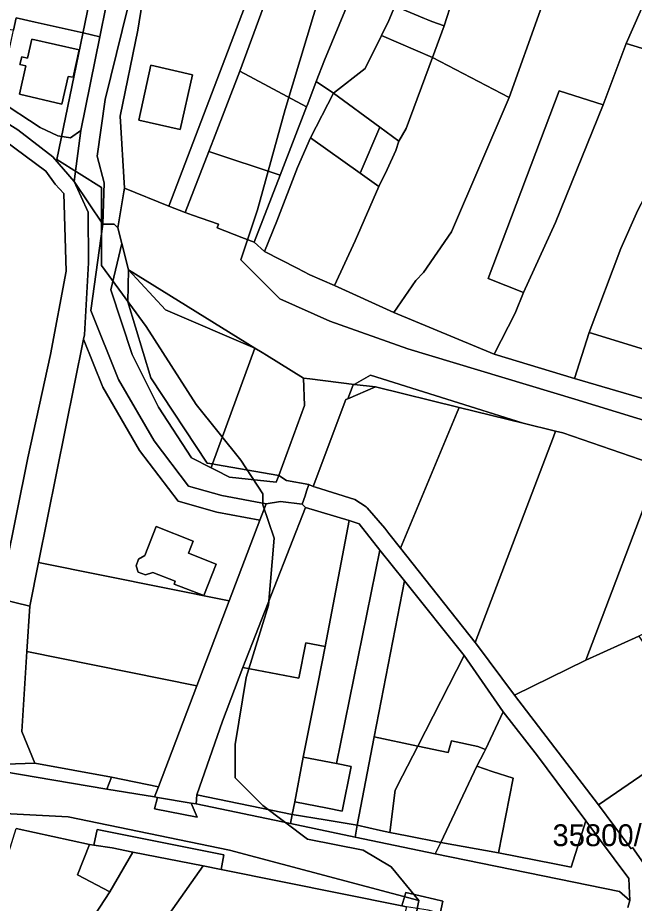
# Model space of a CAD drawing. Extents: x -545779 to -541342, y -1153413 to -1149956.
# Drawn here: x -544345 to -544203.7, y -1151461.6 to -1151258.7 of the extents above; entities that cross this region are included whole.
import ezdxf

# ---------------------------------------------------------------- set-up
doc = ezdxf.new("R2010")
doc.units = 0
for name, color, linetype in [('95560013', 7, 'Continuous'), ('95590013', 7, 'Continuous'), ('95610013', 7, 'Continuous'), ('95630013', 7, 'Continuous'), ('95640013', 7, 'Continuous'), ('95660013', 7, 'Continuous')]:
    doc.layers.add(name, color=color, linetype=linetype)

msp = doc.modelspace()

# ---------------------------------------------------------------- linework, layer by layer
at = {"layer": '95560013'}
for points in [[(-544358.51, -1151276.58), (-544353.61, -1151279.04), (-544353.12, -1151283.1), (-544338.53, -1151293.83), (-544336.38, -1151296.81), (-544334.45, -1151298.99), (-544333.93, -1151316.81), (-544337.5, -1151335.87), (-544342.65, -1151359.51), (-544347.81, -1151384.94), (-544349.21, -1151391.85), (-544356.61, -1151430.05), (-544386.22, -1151427.51), (-544360.6, -1151276)], [(-544332.09, -1151296.26), (-544328.86, -1151303.25), (-544328.78, -1151314.84), (-544329.71, -1151331.38), (-544329.9, -1151332.33), (-544340.23, -1151383.48), (-544342.25, -1151393.49), (-544349.21, -1151391.85), (-544347.81, -1151384.94), (-544342.65, -1151359.51), (-544337.5, -1151335.87), (-544333.93, -1151316.81), (-544334.45, -1151298.99), (-544336.38, -1151296.81), (-544338.53, -1151293.83), (-544353.12, -1151283.1), (-544353.61, -1151279.04), (-544344.97, -1151284.38), (-544336.96, -1151290.58)], [(-544328.22, -1151325.77), (-544321.89, -1151341.58), (-544313.74, -1151355.65), (-544305.84, -1151365.99), (-544298.23, -1151368.17), (-544288.03, -1151370.05), (-544289.48, -1151373.85), (-544299.4, -1151372.02), (-544308.19, -1151369.5), (-544317.07, -1151357.88), (-544325.5, -1151343.33), (-544329.9, -1151332.33), (-544329.71, -1151331.38), (-544328.78, -1151314.84), (-544328.86, -1151303.25), (-544332.09, -1151296.26), (-544325.52, -1151305.99)], [(-544325.5, -1151343.33), (-544317.07, -1151357.88), (-544308.19, -1151369.5), (-544299.4, -1151372.02), (-544289.48, -1151373.85), (-544296.52, -1151392.31), (-544340.23, -1151383.48), (-544329.9, -1151332.33)], [(-544309.16, -1151388.48), (-544302.36, -1151391.08), (-544299.53, -1151383.86), (-544305.85, -1151381.37), (-544304.77, -1151378.59), (-544313.29, -1151375.26), (-544315.88, -1151381.89), (-544317.32, -1151382.78), (-544317.83, -1151384.31), (-544317.41, -1151385.74), (-544315.73, -1151386.35), (-544314.04, -1151385.77), (-544308.89, -1151387.76)], [(-544267.95, -1151509.09), (-544330.23, -1151488.03), (-544321.64, -1151475.91), (-544315.45, -1151471.39), (-544302.52, -1151452.98), (-544298.41, -1151453.81), (-544256.95, -1151462.18), (-544255.94, -1151462.38)]]:
    msp.add_lwpolyline(points, close=True, dxfattribs=at)
at = {"layer": '95590013'}
for points in [[(-544317.48, -1151261.56), (-544310.68, -1151219.21), (-544282.62, -1151229.03), (-544310.36, -1151301.85), (-544320.51, -1151297.8), (-544321.55, -1151281.26)], [(-544278.82, -1151279.15), (-544294.08, -1151270.98), (-544281.27, -1151236.08), (-544264.38, -1151242.96), (-544267.99, -1151252.2), (-544272.99, -1151264.39), (-544274.71, -1151268.41), (-544276.58, -1151273.29), (-544278.55, -1151278.44)], [(-544336.85, -1151254.74), (-544326.33, -1151255.53), (-544324.7, -1151255.9), (-544326.16, -1151263.08), (-544330.01, -1151262.21), (-544341.03, -1151259.73), (-544345.32, -1151258.76), (-544345.94, -1151261.56), (-544359.55, -1151260.12), (-544358.15, -1151252.98), (-544358.05, -1151252.48)], [(-544249.96, -1151267.81), (-544256.01, -1151284.13), (-544257.66, -1151286.99), (-544262, -1151283.8), (-544272.62, -1151276.01), (-544265.41, -1151270.38), (-544261.6, -1151262.8)], [(-544214.06, -1151330.84), (-544217.39, -1151341.34), (-544235.8, -1151335.76), (-544231.01, -1151326.43), (-544229.11, -1151321.68), (-544221.74, -1151305.59), (-544210.83, -1151278.67), (-544205.59, -1151264.63), (-544186.43, -1151270.42), (-544188.28, -1151275.15), (-544202.88, -1151302.79), (-544206.77, -1151311.61)], [(-544267.66, -1151309.79), (-544262.26, -1151297.41), (-544260.35, -1151293.51), (-544258.33, -1151289.17), (-544257.66, -1151286.99), (-544256.01, -1151284.13), (-544249.96, -1151267.81), (-544232.38, -1151276.98), (-544245.59, -1151307.77), (-544252.04, -1151317.08), (-544253.8, -1151318.93), (-544258.81, -1151326.24), (-544272.39, -1151320.03)], [(-544317.27, -1151282.21), (-544307.74, -1151284.33), (-544304.92, -1151271.8), (-544314.47, -1151269.6)], [(-544284.87, -1151294.78), (-544301.19, -1151289.35), (-544300.12, -1151286.59), (-544294.08, -1151270.98), (-544278.82, -1151279.15)], [(-544277.88, -1151286.23), (-544272.62, -1151276.01), (-544262, -1151283.8), (-544266.53, -1151294.35)], [(-544229.11, -1151321.68), (-544237.18, -1151318.45), (-544220.91, -1151275.43), (-544210.83, -1151278.67), (-544221.74, -1151305.59)], [(-544311.14, -1151325.6), (-544290.66, -1151334.39), (-544300.36, -1151360.94), (-544301.59, -1151360.73), (-544314.52, -1151341.22), (-544319.76, -1151323.83), (-544319.64, -1151316.49)], [(-544319.64, -1151316.49), (-544290.66, -1151334.39), (-544311.14, -1151325.6)], [(-544300.36, -1151360.94), (-544290.66, -1151334.39), (-544288.98, -1151335.43), (-544287.98, -1151336.05), (-544279.49, -1151341.29), (-544279.26, -1151347.52), (-544285.19, -1151363.57), (-544299.64, -1151361.07)], [(-544265.13, -1151370.74), (-544267.72, -1151369.06), (-544276.72, -1151366.25), (-544277.27, -1151366.08), (-544269.78, -1151346.21), (-544269.32, -1151346.01), (-544263.04, -1151343.3), (-544243.82, -1151347.99), (-544244.28, -1151349.1), (-544257.27, -1151380.2), (-544259.92, -1151376.85), (-544260.9, -1151375.62), (-544264.92, -1151370.99)], [(-544257.27, -1151380.2), (-544244.28, -1151349.1), (-544243.82, -1151347.99), (-544229.13, -1151351.58), (-544221.72, -1151353.39), (-544222.23, -1151354.73), (-544240.13, -1151401.83)], [(-544220.07, -1151353.81), (-544197.92, -1151361.47), (-544214.8, -1151405.86), (-544231.12, -1151413.87), (-544239.84, -1151402.21), (-544240.13, -1151401.83), (-544222.23, -1151354.73), (-544221.72, -1151353.39)], [(-544184.06, -1151366.1), (-544196.08, -1151397), (-544202.66, -1151400.37), (-544214.8, -1151405.86), (-544197.92, -1151361.47)], [(-544278.98, -1151401.88), (-544280.58, -1151410.03), (-544293.39, -1151407.59), (-544279.01, -1151370.9), (-544269.06, -1151373.86), (-544274.53, -1151402.75)], [(-544274.53, -1151402.75), (-544269.06, -1151373.86), (-544266.73, -1151374.66), (-544261.98, -1151380.65), (-544271.93, -1151429.58), (-544279.58, -1151428.07), (-544278.27, -1151421.65), (-544276.14, -1151410.92)], [(-544256.39, -1151387.69), (-544263.31, -1151423.42), (-544267.18, -1151443.7), (-544274.55, -1151442.49), (-544282.08, -1151441.25), (-544281.48, -1151438.36), (-544274.01, -1151439.82), (-544270.64, -1151440.47), (-544268.6, -1151430.24), (-544271.93, -1151429.58), (-544261.98, -1151380.65)], [(-544253.32, -1151425.56), (-544263.31, -1151423.42), (-544256.39, -1151387.69), (-544242.66, -1151404.79)], [(-544211.87, -1151438.99), (-544231.12, -1151413.87), (-544214.8, -1151405.86), (-544202.66, -1151400.37), (-544191.4, -1151417.5), (-544195.65, -1151419.8), (-544191.7, -1151425.19)], [(-544242.66, -1151404.79), (-544233.72, -1151417.75), (-544237.81, -1151426.35), (-544239.58, -1151425.66), (-544245.58, -1151424.34), (-544246.35, -1151427.05), (-544253.32, -1151425.56)], [(-544239.78, -1151430.15), (-544236.3, -1151431.37), (-544231.43, -1151432.91), (-544234.82, -1151450.04), (-544248.07, -1151447.62)], [(-544331.29, -1151455.07), (-544323.85, -1151458.96), (-544346.93, -1151494.3), (-544356.79, -1151506.85), (-544374.44, -1151524.6), (-544358.92, -1151488.07), (-544345.38, -1151444.48), (-544328.51, -1151448.1)]]:
    msp.add_lwpolyline(points, close=True, dxfattribs=at)
at = {"layer": '95610013'}
for points in [[(-544342.89, -1151403.92), (-544342.25, -1151393.49), (-544340.23, -1151383.48), (-544296.52, -1151392.31), (-544303.94, -1151411.78)], [(-544349.21, -1151391.85), (-544342.25, -1151393.49), (-544342.89, -1151403.92), (-544344.02, -1151422.2), (-544341.1, -1151429.5), (-544356.61, -1151430.05)], [(-544303.94, -1151411.78), (-544312.77, -1151434.93), (-544323.5, -1151432.72), (-544341.1, -1151429.5), (-544344.02, -1151422.2), (-544342.89, -1151403.92)]]:
    msp.add_lwpolyline(points, close=True, dxfattribs=at)
at = {"layer": '95630013'}
for points in [[(-544310.68, -1151219.21), (-544317.48, -1151261.56), (-544321.55, -1151281.26), (-544320.51, -1151297.8), (-544320.65, -1151298.6), (-544322.04, -1151306.84), (-544322.89, -1151306.03), (-544323.14, -1151306.03), (-544324.13, -1151306.01), (-544325.52, -1151305.99), (-544325.19, -1151296.57), (-544326.79, -1151290.45), (-544324.93, -1151277.46), (-544319.79, -1151256.39)], [(-544205.17, -1151462.51), (-544204.74, -1151460.96), (-544204.92, -1151455.91), (-544214.78, -1151442.66), (-544225.87, -1151427.83), (-544233.72, -1151417.75), (-544242.66, -1151404.79), (-544256.39, -1151387.69), (-544261.98, -1151380.65), (-544266.73, -1151374.66), (-544269.06, -1151373.86), (-544279.01, -1151370.9), (-544279.78, -1151370.16), (-544279.14, -1151368.23), (-544278.97, -1151367.71), (-544278.79, -1151367.18), (-544278.29, -1151365.66), (-544277.27, -1151366.08), (-544276.72, -1151366.25), (-544267.72, -1151369.06), (-544265.13, -1151370.74), (-544264.92, -1151370.99), (-544260.9, -1151375.62), (-544259.92, -1151376.85), (-544257.27, -1151380.2), (-544240.13, -1151401.83), (-544239.84, -1151402.21), (-544231.12, -1151413.87), (-544211.87, -1151438.99), (-544204.38, -1151449.08), (-544204.14, -1151448.78), (-544196.56, -1151459.57)]]:
    msp.add_lwpolyline(points, dxfattribs=at)
for points in [[(-544296.44, -1151363.94), (-544285.76, -1151365.11), (-544285.19, -1151363.57), (-544283.37, -1151364.7), (-544278.29, -1151365.66), (-544278.79, -1151367.18), (-544278.97, -1151367.71), (-544279.14, -1151368.23), (-544279.78, -1151370.16), (-544284.74, -1151369.56), (-544288.03, -1151370.05), (-544298.23, -1151368.17), (-544305.84, -1151365.99), (-544313.74, -1151355.65), (-544321.89, -1151341.58), (-544328.22, -1151325.77), (-544325.52, -1151305.99), (-544324.13, -1151306.01), (-544323.14, -1151306.03), (-544322.89, -1151306.03), (-544322.04, -1151306.84), (-544321.15, -1151310.42), (-544323.69, -1151321.04), (-544318.74, -1151335.85), (-544312.7, -1151347.96), (-544305.15, -1151359.53), (-544300.67, -1151361.8), (-544299.57, -1151362.36)], [(-544312.7, -1151347.96), (-544318.74, -1151335.85), (-544323.69, -1151321.04), (-544321.15, -1151310.42), (-544319.64, -1151316.49), (-544319.76, -1151323.83), (-544314.52, -1151341.22), (-544301.59, -1151360.73), (-544300.36, -1151360.94), (-544300.67, -1151361.8), (-544305.15, -1151359.53)], [(-544300.67, -1151361.8), (-544300.36, -1151360.94), (-544299.64, -1151361.07), (-544285.19, -1151363.57), (-544285.76, -1151365.11), (-544296.44, -1151363.94), (-544299.57, -1151362.36)]]:
    msp.add_lwpolyline(points, close=True, dxfattribs=at)
at = {"layer": '95640013'}
for points in [[(-544325.19, -1151296.57), (-544325.52, -1151305.99), (-544332.09, -1151296.26), (-544330.54, -1151284.54), (-544326.16, -1151263.08), (-544324.7, -1151255.9), (-544320.53, -1151230.04), (-544319.5, -1151209.97), (-544319, -1151203.45), (-544317.52, -1151169.14), (-544317.04, -1151147.53), (-544317.86, -1151142.3), (-544318.04, -1151141.16), (-544316.85, -1151140.73), (-544311.08, -1151144.88), (-544311.16, -1151145.77), (-544314.11, -1151209.76), (-544315.77, -1151230.23), (-544317.56, -1151243.24), (-544319.79, -1151256.39), (-544324.93, -1151277.46), (-544326.79, -1151290.45)], [(-544270.44, -1151209), (-544278.93, -1151230.53), (-544281.27, -1151236.08), (-544294.08, -1151270.98), (-544300.12, -1151286.59), (-544301.19, -1151289.35), (-544306.65, -1151303.34), (-544310.36, -1151301.85), (-544282.62, -1151229.03), (-544310.68, -1151219.21), (-544296.94, -1151220.15), (-544295.98, -1151210.19), (-544284.56, -1151211.3), (-544281.03, -1151208.99), (-544271.73, -1151209.97), (-544271.45, -1151208.83)], [(-544233.95, -1151221.19), (-544215.15, -1151228.39), (-544218.13, -1151237.23), (-544232.38, -1151276.98), (-544249.96, -1151267.81), (-544247.29, -1151260.6), (-544245.37, -1151254.55), (-544242.89, -1151247.57), (-544240.19, -1151239.83), (-544239.06, -1151236.62), (-544237.79, -1151232.99), (-544236.76, -1151230.1), (-544237.09, -1151229.98)], [(-544192.11, -1151232.82), (-544195.39, -1151241.43), (-544195.59, -1151241.96), (-544198.2, -1151248.07), (-544200.63, -1151253.34), (-544205.59, -1151264.63), (-544210.83, -1151278.67), (-544220.91, -1151275.43), (-544237.18, -1151318.45), (-544229.11, -1151321.68), (-544231.01, -1151326.43), (-544235.8, -1151335.76), (-544258.81, -1151326.24), (-544253.8, -1151318.93), (-544252.04, -1151317.08), (-544245.59, -1151307.77), (-544232.38, -1151276.98), (-544218.13, -1151237.23), (-544215.15, -1151228.39)], [(-544195.59, -1151241.96), (-544195.39, -1151241.43), (-544192.11, -1151232.82), (-544172.85, -1151235.23), (-544173, -1151235.65), (-544175.98, -1151243.88), (-544176.46, -1151245.09), (-544186.43, -1151270.42), (-544205.59, -1151264.63), (-544200.63, -1151253.34), (-544198.2, -1151248.07)], [(-544183.39, -1151291.3), (-544184.77, -1151291.38), (-544198.77, -1151312.95), (-544197.8, -1151315.18), (-544187.84, -1151320.21), (-544192.28, -1151332.61), (-544200.34, -1151331.28), (-544201.39, -1151334.72), (-544214.06, -1151330.84), (-544206.77, -1151311.61), (-544202.88, -1151302.79), (-544188.28, -1151275.15), (-544186.43, -1151270.42), (-544176.46, -1151245.09), (-544175.98, -1151243.88), (-544173, -1151235.65), (-544172.85, -1151235.23), (-544147.79, -1151238.88), (-544152.83, -1151248.37), (-544158.38, -1151257.07), (-544170.37, -1151278.58), (-544172.24, -1151282.28), (-544178.37, -1151293.74)], [(-544267.99, -1151252.2), (-544264.38, -1151242.96), (-544263.32, -1151240.24), (-544257.78, -1151242.16), (-544252.61, -1151244.35), (-544242.89, -1151247.57), (-544245.37, -1151254.55), (-544247.29, -1151260.6), (-544250.08, -1151259.56), (-544251.02, -1151259.2), (-544251.79, -1151258.91), (-544257.42, -1151256.53), (-544258.6, -1151256.09), (-544262.6, -1151254.38)], [(-544267.99, -1151252.2), (-544262.6, -1151254.38), (-544258.6, -1151256.09), (-544259.95, -1151259.34), (-544261.6, -1151262.8), (-544265.41, -1151270.38), (-544272.62, -1151276.01), (-544276.58, -1151273.29), (-544274.71, -1151268.41), (-544272.99, -1151264.39)], [(-544259.95, -1151259.34), (-544258.6, -1151256.09), (-544257.42, -1151256.53), (-544251.79, -1151258.91), (-544251.02, -1151259.2), (-544250.08, -1151259.56), (-544247.29, -1151260.6), (-544249.96, -1151267.81), (-544261.6, -1151262.8)], [(-544332.89, -1151286.27), (-544335.78, -1151285.78), (-544339.82, -1151283.83), (-544349.44, -1151277.57), (-544346.17, -1151262.61), (-544345.94, -1151261.56), (-544345.32, -1151258.76), (-544341.03, -1151259.73), (-544330.01, -1151262.21), (-544326.16, -1151263.08), (-544330.54, -1151284.54)], [(-544342.74, -1151267.98), (-544344.03, -1151267.65), (-544344.49, -1151269.47), (-544343.1, -1151269.73), (-544344.62, -1151276.24), (-544334.85, -1151278.51), (-544333.4, -1151272.19), (-544332.32, -1151272.35), (-544330.88, -1151266.06), (-544341.77, -1151263.6)], [(-544334.85, -1151278.51), (-544344.62, -1151276.24), (-544343.1, -1151269.73), (-544344.49, -1151269.47), (-544344.03, -1151267.65), (-544342.74, -1151267.98), (-544341.77, -1151263.6), (-544330.88, -1151266.06), (-544332.32, -1151272.35), (-544333.4, -1151272.19)], [(-544317.27, -1151282.21), (-544314.47, -1151269.6), (-544304.92, -1151271.8), (-544307.74, -1151284.33)], [(-544285.65, -1151305.31), (-544288.41, -1151312.26), (-544290.82, -1151310.16), (-544284.87, -1151294.78), (-544278.82, -1151279.15), (-544278.55, -1151278.44), (-544276.58, -1151273.29), (-544272.62, -1151276.01), (-544277.88, -1151286.23), (-544280.91, -1151293.03)], [(-544257.66, -1151286.99), (-544258.33, -1151289.17), (-544260.35, -1151293.51), (-544262.26, -1151297.41), (-544266.53, -1151294.35), (-544262, -1151283.8)], [(-544267.66, -1151309.79), (-544272.39, -1151320.03), (-544278.04, -1151317.64), (-544280.95, -1151316.12), (-544288.41, -1151312.26), (-544285.65, -1151305.31), (-544280.91, -1151293.03), (-544277.88, -1151286.23), (-544266.53, -1151294.35), (-544262.26, -1151297.41)], [(-544284.87, -1151294.78), (-544290.82, -1151310.16), (-544293.65, -1151309.1), (-544299.32, -1151306.86), (-544298.99, -1151306.02), (-544304.91, -1151303.91), (-544306.65, -1151303.34), (-544301.19, -1151289.35)], [(-544201.39, -1151334.72), (-544200.34, -1151331.28), (-544192.28, -1151332.61), (-544192.54, -1151334.15), (-544193.05, -1151337.27), (-544194.14, -1151343.85), (-544194.96, -1151347.93), (-544217.39, -1151341.34), (-544214.06, -1151330.84)], [(-544269.78, -1151346.21), (-544277.27, -1151366.08), (-544278.29, -1151365.66), (-544283.37, -1151364.7), (-544285.19, -1151363.57), (-544279.26, -1151347.52), (-544279.49, -1151341.29), (-544278.08, -1151341.46), (-544267.92, -1151342.7), (-544268.15, -1151342.83), (-544269.32, -1151346.01)], [(-544263.04, -1151343.3), (-544267.92, -1151342.7), (-544264.14, -1151340.57), (-544229.13, -1151351.58), (-544243.82, -1151347.99)], [(-544267.92, -1151342.7), (-544263.04, -1151343.3), (-544269.32, -1151346.01), (-544268.15, -1151342.83)], [(-544293.39, -1151407.59), (-544298.08, -1151419.85), (-544303.98, -1151436.74), (-544304.11, -1151438.8), (-544305.28, -1151438.61), (-544312.98, -1151437.32), (-544313.64, -1151437.21), (-544312.77, -1151434.93), (-544303.94, -1151411.78), (-544296.52, -1151392.31), (-544289.48, -1151373.85), (-544288.03, -1151370.05), (-544284.74, -1151369.56), (-544279.78, -1151370.16), (-544279.01, -1151370.9)], [(-544317.32, -1151382.78), (-544315.88, -1151381.89), (-544313.29, -1151375.26), (-544304.77, -1151378.59), (-544305.85, -1151381.37), (-544299.53, -1151383.86), (-544302.36, -1151391.08), (-544309.16, -1151388.48), (-544308.89, -1151387.76), (-544314.04, -1151385.77), (-544315.73, -1151386.35), (-544317.41, -1151385.74), (-544317.83, -1151384.31)], [(-544293.39, -1151407.59), (-544280.58, -1151410.03), (-544278.98, -1151401.88), (-544274.53, -1151402.75), (-544276.14, -1151410.92), (-544278.27, -1151421.65), (-544279.58, -1151428.07), (-544281.48, -1151438.36), (-544282.08, -1151441.25), (-544303.98, -1151436.74), (-544298.08, -1151419.85)], [(-544237.81, -1151426.35), (-544233.72, -1151417.75), (-544225.87, -1151427.83), (-544214.78, -1151442.66), (-544218.14, -1151453.31), (-544222.02, -1151452.57), (-544234.82, -1151450.04), (-544231.43, -1151432.91), (-544236.3, -1151431.37), (-544239.78, -1151430.15), (-544238.13, -1151426.97)], [(-544263.31, -1151423.42), (-544253.32, -1151425.56), (-544256.85, -1151432.41), (-544258.52, -1151435.68), (-544259.72, -1151445.33), (-544261.88, -1151444.9), (-544267.18, -1151443.7)], [(-544256.85, -1151432.41), (-544253.32, -1151425.56), (-544246.35, -1151427.05), (-544245.58, -1151424.34), (-544239.58, -1151425.66), (-544237.81, -1151426.35), (-544238.13, -1151426.97), (-544239.78, -1151430.15), (-544248.07, -1151447.62), (-544255.75, -1151446.11), (-544259.72, -1151445.33), (-544258.52, -1151435.68)], [(-544187.56, -1151430.91), (-544181.53, -1151438.55), (-544179.83, -1151440.76), (-544175.55, -1151448.78), (-544192.77, -1151457.73), (-544196.56, -1151459.57), (-544204.14, -1151448.78), (-544204.38, -1151449.08), (-544211.87, -1151438.99), (-544191.7, -1151425.19)], [(-544281.48, -1151438.36), (-544279.58, -1151428.07), (-544271.93, -1151429.58), (-544268.6, -1151430.24), (-544270.64, -1151440.47), (-544274.01, -1151439.82)], [(-544341.1, -1151429.5), (-544323.5, -1151432.72), (-544324.56, -1151435.4), (-544356.61, -1151430.05)], [(-544324.56, -1151435.4), (-544323.5, -1151432.72), (-544312.77, -1151434.93), (-544313.64, -1151437.21)], [(-544303.87, -1151441.87), (-544313.68, -1151439.94), (-544312.98, -1151437.32), (-544305.28, -1151438.61)], [(-544282.51, -1151443.31), (-544304.11, -1151438.8), (-544303.98, -1151436.74), (-544282.08, -1151441.25)], [(-544267.69, -1151446.4), (-544282.51, -1151443.31), (-544282.08, -1151441.25), (-544274.55, -1151442.49), (-544267.18, -1151443.7)], [(-544214.78, -1151442.66), (-544204.92, -1151455.91), (-544204.74, -1151460.96), (-544207.08, -1151458.91), (-544249.31, -1151450.22), (-544248.07, -1151447.62), (-544234.82, -1151450.04), (-544222.02, -1151452.57), (-544218.14, -1151453.31)], [(-544323.36, -1151448.87), (-544327.52, -1151448.25), (-544326.81, -1151444.64), (-544297.78, -1151450.46), (-544298.41, -1151453.81), (-544302.52, -1151452.98), (-544318.6, -1151449.9)], [(-544267.69, -1151446.4), (-544267.18, -1151443.7), (-544261.88, -1151444.9), (-544259.72, -1151445.33), (-544255.75, -1151446.11), (-544248.07, -1151447.62), (-544249.31, -1151450.22)], [(-544331.29, -1151455.07), (-544328.51, -1151448.1), (-544327.52, -1151448.25), (-544323.36, -1151448.87), (-544318.6, -1151449.9), (-544323.85, -1151458.96)], [(-544256.95, -1151462.18), (-544256.08, -1151459.1), (-544249.52, -1151460.65), (-544247.56, -1151461.12), (-544248.15, -1151463.92), (-544250.9, -1151463.17), (-544255.94, -1151462.38)]]:
    msp.add_lwpolyline(points, close=True, dxfattribs=at)
for points in [[(-544517.96, -1151238.54), (-544416.31, -1151258.67), (-544376.33, -1151267.55), (-544361.72, -1151271.16), (-544352.01, -1151275.9), (-544349.44, -1151277.57), (-544339.82, -1151283.83), (-544335.78, -1151285.78), (-544332.89, -1151286.27), (-544330.54, -1151284.54), (-544332.09, -1151296.26), (-544336.96, -1151290.58), (-544344.97, -1151284.38), (-544353.61, -1151279.04), (-544358.51, -1151276.58), (-544360.6, -1151276), (-544376.21, -1151271.68), (-544380.12, -1151272.95), (-544381.96, -1151272.53), (-544406.01, -1151267.06), (-544518.88, -1151243.65)], [(-544197.92, -1151361.47), (-544220.07, -1151353.81), (-544221.72, -1151353.39), (-544229.13, -1151351.58), (-544264.14, -1151340.57), (-544267.92, -1151342.7), (-544278.08, -1151341.46), (-544279.49, -1151341.29), (-544287.98, -1151336.05), (-544288.98, -1151335.43), (-544290.66, -1151334.39), (-544319.64, -1151316.49), (-544321.15, -1151310.42), (-544322.04, -1151306.84), (-544320.65, -1151298.6), (-544320.51, -1151297.8), (-544310.36, -1151301.85), (-544306.65, -1151303.34), (-544304.91, -1151303.91), (-544298.99, -1151306.02), (-544299.32, -1151306.86), (-544293.65, -1151309.1), (-544290.82, -1151310.16), (-544288.41, -1151312.26), (-544280.95, -1151316.12), (-544278.04, -1151317.64), (-544272.39, -1151320.03), (-544258.81, -1151326.24), (-544235.8, -1151335.76), (-544217.39, -1151341.34), (-544194.96, -1151347.93)], [(-544356.61, -1151430.05), (-544324.56, -1151435.4), (-544313.64, -1151437.21), (-544312.98, -1151437.32), (-544313.68, -1151439.94), (-544303.87, -1151441.87), (-544305.28, -1151438.61), (-544304.11, -1151438.8), (-544282.51, -1151443.31), (-544267.69, -1151446.4), (-544249.31, -1151450.22), (-544207.08, -1151458.91), (-544204.74, -1151460.96), (-544205.17, -1151462.51)], [(-544248.15, -1151463.92), (-544247.56, -1151461.12), (-544249.52, -1151460.65), (-544256.08, -1151459.1), (-544256.95, -1151462.18), (-544298.41, -1151453.81), (-544297.78, -1151450.46), (-544326.81, -1151444.64), (-544327.52, -1151448.25), (-544328.51, -1151448.1), (-544345.38, -1151444.48)], [(-544455.29, -1151722.05), (-544425.47, -1151635.75), (-544402.51, -1151579.84), (-544385.47, -1151546.37), (-544374.44, -1151524.6), (-544356.79, -1151506.85), (-544346.93, -1151494.3), (-544323.85, -1151458.96), (-544318.6, -1151449.9), (-544302.52, -1151452.98), (-544315.45, -1151471.39), (-544321.64, -1151475.91), (-544330.23, -1151488.03), (-544348.98, -1151514.49), (-544374.27, -1151550.18), (-544385.88, -1151566.12), (-544411.63, -1151619.63), (-544415.57, -1151630.49), (-544431.97, -1151675.83)]]:
    msp.add_lwpolyline(points, dxfattribs=at)
at = {"layer": '95660013'}
for points in [[(-544200.752, -1151481.323), (-544182.888, -1151455.804), (-544167.577, -1151443.044), (-544134.401, -1151429.009), (-544108.882, -1151416.249), (-544097.399, -1151407.317), (-544089.743, -1151397.11), (-544092.294, -1151381.798), (-544097.399, -1151374.142), (-544103.778, -1151371.59), (-544121.642, -1151367.762), (-544159.921, -1151362.659), (-544184.164, -1151356.279), (-544217.338, -1151346.071), (-544255.618, -1151334.587), (-544273.482, -1151328.207), (-544284.965, -1151323.104), (-544293.897, -1151314.172), (-544290.07, -1151302.688), (-544283.689, -1151279.721), (-544272.206, -1151241.442)], [(-544272.206, -1151241.442), (-544283.689, -1151279.721), (-544290.07, -1151302.688), (-544293.897, -1151314.172), (-544284.965, -1151323.104), (-544273.482, -1151328.207), (-544255.618, -1151334.587), (-544217.338, -1151346.071), (-544184.164, -1151356.279), (-544159.921, -1151362.659), (-544121.642, -1151367.762), (-544103.778, -1151371.59), (-544097.399, -1151374.142), (-544092.294, -1151381.798), (-544089.743, -1151397.11), (-544097.399, -1151407.317), (-544108.882, -1151416.249), (-544134.401, -1151429.009), (-544167.577, -1151443.044), (-544182.888, -1151455.804), (-544200.752, -1151481.323)], [(-544327.072, -1151247.821), (-544336.004, -1151291.204), (-544325.796, -1151297.584), (-544325.796, -1151315.448), (-544315.588, -1151329.483), (-544304.105, -1151347.347), (-544293.897, -1151360.107), (-544288.794, -1151367.762), (-544288.794, -1151370.314), (-544286.241, -1151377.97), (-544287.518, -1151393.282), (-544292.621, -1151409.869), (-544295.173, -1151425.181), (-544295.173, -1151432.837), (-544288.794, -1151439.216), (-544278.585, -1151446.872), (-544265.825, -1151449.424), (-544259.445, -1151453.252), (-544253.066, -1151460.908), (-544296.449, -1151449.424), (-544333.452, -1151441.768), (-544383.215, -1151439.216), (-544475.085, -1151436.665), (-544512.088, -1151439.216)], [(-544301.51, -1151661.3), (-544292.621, -1151633.163), (-544283.689, -1151588.505), (-544261.998, -1151506.843), (-544253.066, -1151460.908), (-544259.445, -1151453.252), (-544265.825, -1151449.424), (-544278.585, -1151446.872), (-544288.794, -1151439.216), (-544295.173, -1151432.837), (-544295.173, -1151425.181), (-544292.621, -1151409.869), (-544287.518, -1151393.282), (-544286.241, -1151377.97), (-544288.794, -1151370.314), (-544288.794, -1151367.762), (-544293.897, -1151360.107), (-544304.105, -1151347.347), (-544315.588, -1151329.483), (-544325.796, -1151315.448), (-544325.796, -1151297.584), (-544336.004, -1151291.204), (-544327.072, -1151247.821)], [(-544512.088, -1151439.216), (-544475.085, -1151436.665), (-544383.215, -1151439.216), (-544333.452, -1151441.768), (-544296.449, -1151449.424), (-544253.066, -1151460.908), (-544261.998, -1151506.843), (-544283.689, -1151588.505), (-544301.553, -1151594.884), (-544323.245, -1151605.092), (-544339.831, -1151610.196), (-544353.868, -1151612.748), (-544381.939, -1151610.196), (-544415.114, -1151598.712), (-544453.393, -1151582.125), (-544478.912, -1151569.365), (-544518.467, -1151561.709)]]:
    msp.add_lwpolyline(points, dxfattribs=at)

# ---------------------------------------------------------------- texts
msp.add_text('35800/II.', height=5, rotation=0, dxfattribs=at).set_placement((-544222.443, -1151448.489))

doc.saveas('drawing.dxf')
